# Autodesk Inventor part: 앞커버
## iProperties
Company: 한국ATC센터
Created: 2014-01
Part Number: 앞커버
Document SubType Name: Modeling
Designer: KYOUNG IL JANG
Density: 1 g/cm^3
Material: 기본값
Mass: 88.8969 g
Surface Area: 235.103 cm^2
Volume: 88.8969 cm^3
Vendor: CBT Solutions
Author: KYOUNG IL JANG
